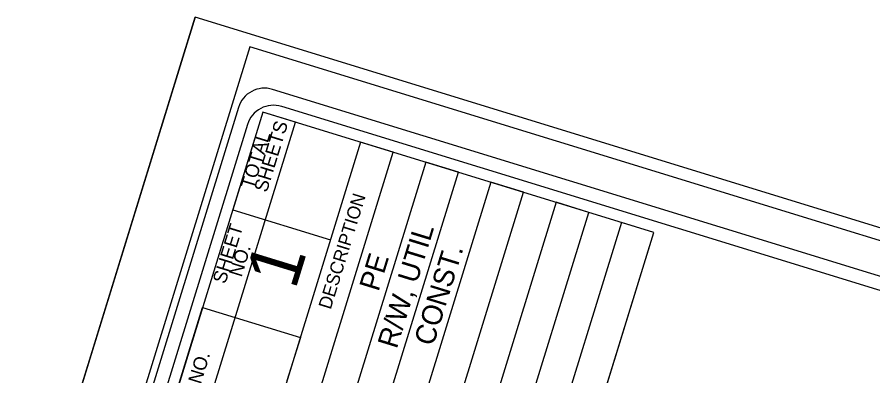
# Model space of a CAD drawing. Extents: x 1347947 to 1350662, y 1027710 to 1030532.
# Drawn here: x 1348377.3 to 1348690.9, y 1030035.7 to 1030167.4 of the extents above; entities that cross this region are included whole.
import ezdxf

# ---------------------------------------------------------------- set-up
doc = ezdxf.new("R2010")
doc.units = 0
for name, color, linetype in [('Sheet Cutting Line CELL', 7, 'Continuous'), ('Sheet Data Field CELL', 7, 'Continuous'), ('Sheet Plot Border Inside CELL', 7, 'Continuous'), ('Sheet Plot Border Outside CELL', 7, 'Continuous'), ('Sheet Title CELL', 7, 'Continuous')]:
    doc.layers.add(name, color=color, linetype=linetype)

msp = doc.modelspace()

# ---------------------------------------------------------------- linework, layer by layer
at = {"layer": 'Sheet Cutting Line CELL'}
msp.add_line((1347946.88, 1028557.97), (1348442.51, 1030167.38), dxfattribs=at)
at = {"layer": 'Sheet Plot Border Inside CELL'}
msp.add_lwpolyline([(1348980.53, 1028253.25), (1349471, 1029845.94), (1348462.64, 1030156.47), (1347972.16, 1028563.78)], close=True, dxfattribs=at)
at = {"layer": 'Sheet Plot Border Outside CELL'}
msp.add_lwpolyline([(1348442.51, 1030167.38), (1347946.88, 1028557.97), (1348998.14, 1028234.22), (1349493.77, 1029843.63)], close=True, dxfattribs=at)
at = {"layer": 'Sheet Title CELL'}
for points in [[(1349455.32, 1029837.69), (1348470.95, 1030140.83)], [(1348458.46, 1030134.23), (1348022.85, 1028719.76)], [(1348398.35, 1029866.03), (1348479.28, 1030128.85), (1348467.34, 1030132.53), (1348386.41, 1029869.7)], [(1348583.7, 1030000.74), (1348610.69, 1030088.38), (1348467.34, 1030132.53), (1348456.3, 1030096.69), (1348492.14, 1030085.66)], [(1349272.28, 1029888.83), (1348474.25, 1030134.58)], [(1348461.76, 1030127.97), (1348043.83, 1028770.87)], [(1348434.2, 1029854.99), (1348515.13, 1030117.81), (1348503.18, 1030121.49), (1348422.24, 1029858.67)], [(1348458.09, 1029847.63), (1348539.01, 1030110.45), (1348527.08, 1030114.13), (1348446.14, 1029851.31)], [(1348481.97, 1029840.28), (1348562.91, 1030103.1), (1348550.96, 1030106.77), (1348470.02, 1029843.95)], [(1348505.87, 1029832.91), (1348586.81, 1030095.73), (1348574.87, 1030099.41), (1348493.93, 1029836.61)], [(1348529.76, 1029825.56), (1348610.69, 1030088.38), (1348598.76, 1030092.05), (1348517.81, 1029829.24)], [(1348397.44, 1029905.55), (1348445.28, 1030060.86), (1348481.1, 1030049.81), (1348476.19, 1030033.85)]]:
    msp.add_lwpolyline(points, dxfattribs=at)
for centre in [(1348467.96, 1030131.29), (1348471.26, 1030125.04)]:
    msp.add_arc(centre, 10, 72.8834, 162.8834, dxfattribs=at)

# ---------------------------------------------------------------- texts
at = {"layer": 'Sheet Data Field CELL'}
for s, p in [('R/W, UTIL ', (1348516.41, 1030045.37)), ('CONST.', (1348529.79, 1030046.34)), ('PE', (1348509.71, 1030066.4))]:
    msp.add_text(s, height=7.5, rotation=72.8834, dxfattribs=at).set_placement(p)
at = {"layer": 'Sheet Title CELL'}
for s, height, p in [('SHEETS', 5, (1348468.79, 1030102.77)), ('TOTAL', 5, (1348463.91, 1030103.92)), ('DESCRIPTION', 4.8, (1348492.21, 1030059.84)), ('SHEET', 5, (1348453.61, 1030069.21)), ('NO.', 5, (1348459.55, 1030071.73)), ('1', 19.35, (1348479.22, 1030066.98)), ('STATE PROJECT REFERENCE NO.', 4.9998, (1348415.33, 1029937.29))]:
    msp.add_text(s, height=height, rotation=72.8834, dxfattribs=at).set_placement(p)

doc.saveas('drawing.dxf')
